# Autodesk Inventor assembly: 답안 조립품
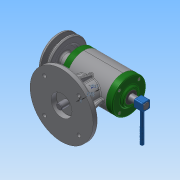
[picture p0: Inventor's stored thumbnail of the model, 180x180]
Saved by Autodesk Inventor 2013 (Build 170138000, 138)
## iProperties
Created: 2017-02
Part Number: 답안 조립품
Document SubType Name: Assembly
Designer: Administrator
Author: Administrator
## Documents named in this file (16)
- C:\Users\Administrator\Desktop\370208V1018\답안 조립품.iam
- C:\Users\Administrator\Desktop\370208V1018\V벨트풀리.ipt
- C:\Users\Administrator\Desktop\370208V1018\뒤커버.ipt
- C:\Users\Administrator\Desktop\370208V1018\레버.ipt
- C:\Users\Administrator\Desktop\370208V1018\멈춤나사 M3x8.ipt
- C:\Users\Administrator\Desktop\370208V1018\베어링 6201.ipt
- C:\Users\Administrator\Desktop\370208V1018\베어링 6202.ipt
- C:\Users\Administrator\Desktop\370208V1018\본체.ipt
- C:\Users\Administrator\Desktop\370208V1018\본체상부커버.ipt
- C:\Users\Administrator\Desktop\370208V1018\볼트 M3x0.5x8.ipt
- C:\Users\Administrator\Desktop\370208V1018\슬라이드.ipt
- C:\Users\Administrator\Desktop\370208V1018\앞커버.ipt
- C:\Users\Administrator\Desktop\370208V1018\오일실 12 22 7.ipt
- C:\Users\Administrator\Desktop\370208V1018\키 4 x 4 x 18.ipt
- C:\Users\Administrator\Desktop\370208V1018\편심축.ipt
- C:\Users\Administrator\Desktop\370208V1018\가변스프링.ipt
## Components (2 placed, 2 different names)
1. V벨트풀리:1
2. 가변스프링:1
